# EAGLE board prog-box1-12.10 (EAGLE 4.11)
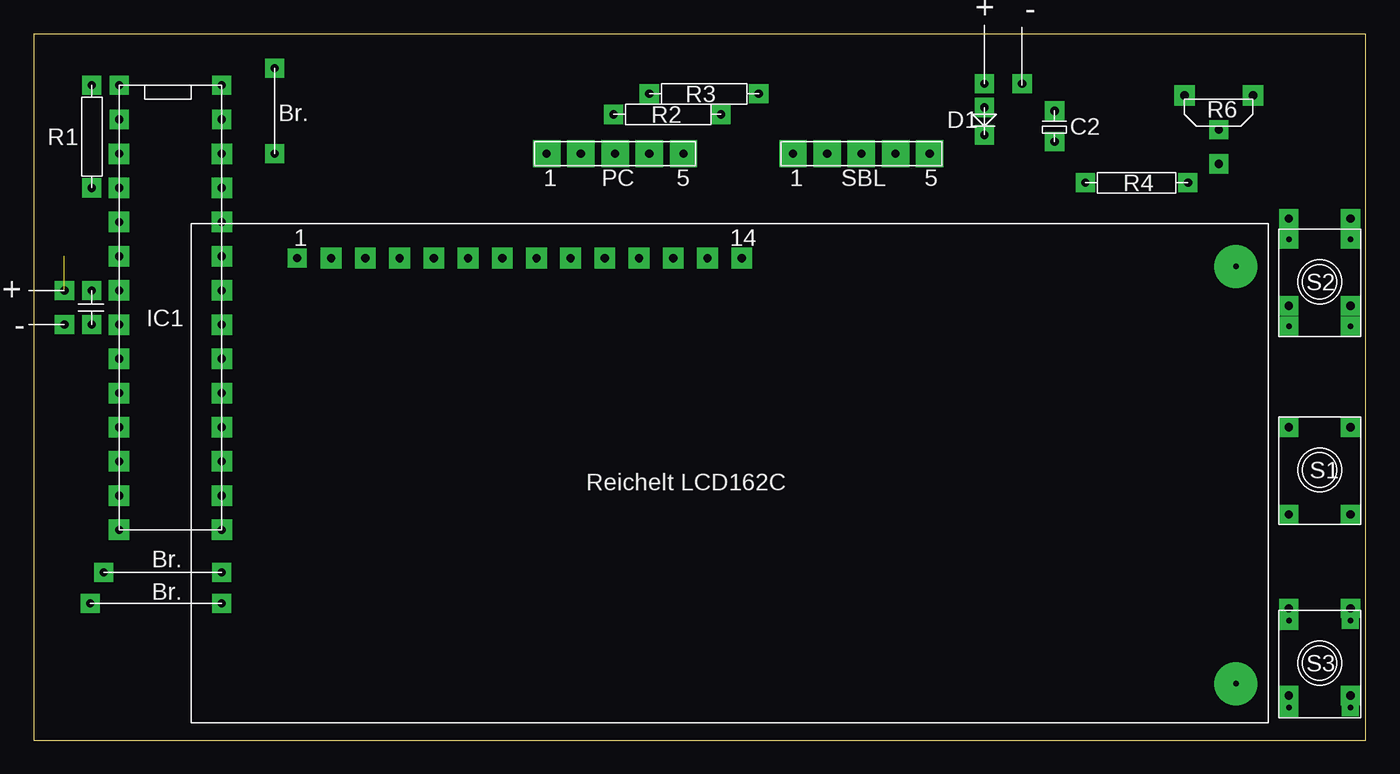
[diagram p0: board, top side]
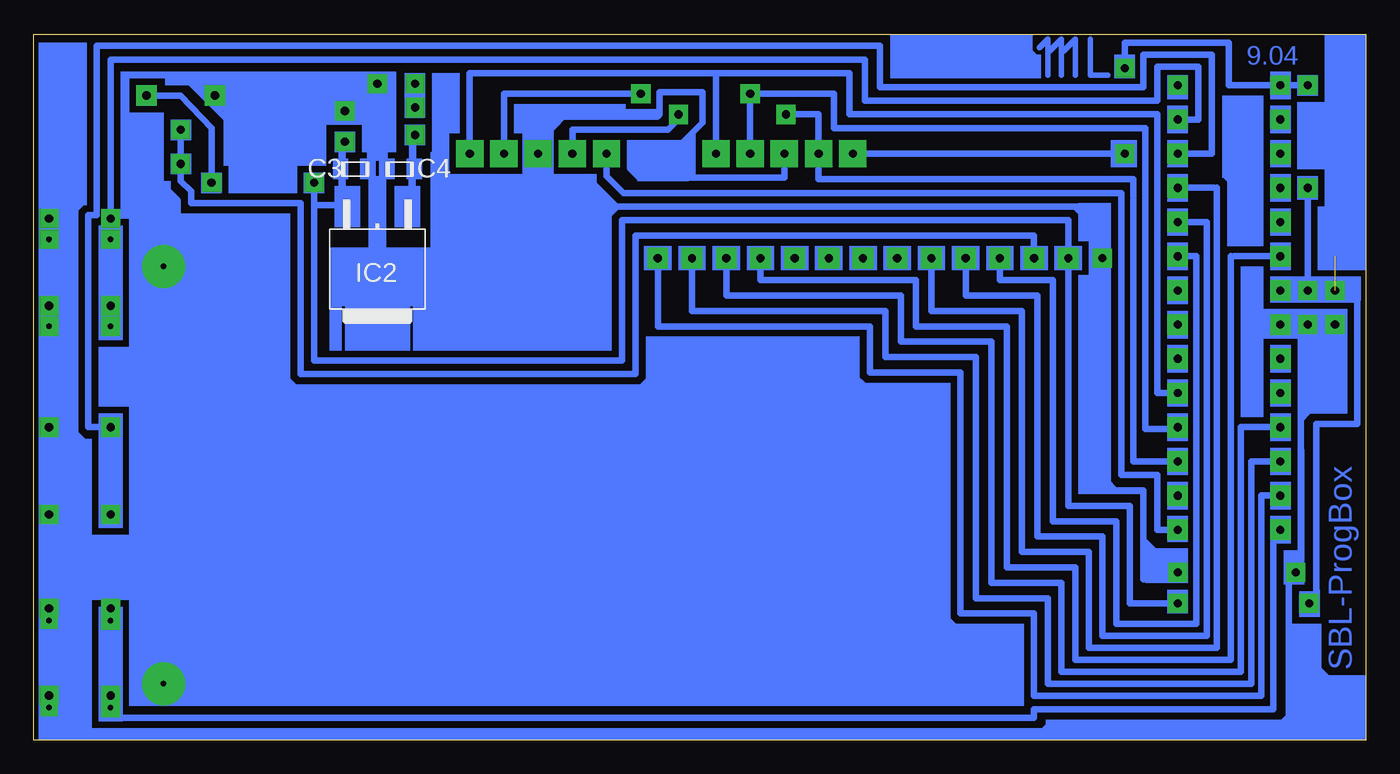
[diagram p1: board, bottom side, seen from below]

Size 98.93 x 52.45 mm. Coordinates in mm from the lower left corner, seen from the top.
Outline: 0,0 98.93,0 98.93,52.45 0,52.45 0,0
Copper layers (1*16): Top 0.035mm / dielectric 1.5mm / Bottom 0.035mm
Design rules "default": minimum track width 10mil, minimum drill 24mil, track to track 8mil, track to pad 8mil, pad to pad 8mil, via to via 8mil, smd to smd 8mil, copper to edge 40mil, drill to drill 8mil, minimum pad ring 10mil, minimum via ring 8mil, stop-mask expansion 4mil, vias tented up to drill 0mil, thermal gap 10mil

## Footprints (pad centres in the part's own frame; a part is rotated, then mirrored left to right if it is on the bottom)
LÖTMF = drill 0.61 pad 1.524 square: P$1 0,0; P$2 2.54,0; P$3 -2.54,0
LÖTP3 = drill 0.61 pad 1.422 square: P$1 0,0
LÖTD = drill 0.61 pad 1.524 square: P$2 2.54,0; P$3 -2.54,0

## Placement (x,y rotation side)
E$1  [LÖTMF]  6.35,18.16 90 top
E$2  [LÖTMF]  6.35,25.78 90 top
E$3  [LÖTMF]  6.35,33.4 90 top
E$4  [LÖTMF]  6.35,41.02 90 top
E$5  [LÖTP3]  6.35,46.1 0 top
E$6  [LÖTP3]  6.35,48.64 0 top
E$7  [LÖTMF]  13.97,18.16 90 top
E$8  [LÖTMF]  13.97,25.78 90 top
E$9  [LÖTMF]  13.97,33.4 90 top
E$10  [LÖTMF]  13.97,41.02 90 top
E$11  [LÖTP3]  13.97,46.1 0 top
E$12  [LÖTP3]  13.97,48.64 0 top
E$13  [LÖTMF]  50.04,35.81 180 top
E$14  [LÖTMF]  42.42,35.81 180 top
E$15  [LÖTMF]  34.8,35.81 180 top
E$16  [LÖTMF]  27.18,35.81 180 top
E$17  [LÖTP3]  22.1,35.81 90 top
E$18  [LÖTP3]  19.56,35.81 90 top
E$19  [LÖTMF]  45.72,43.56 180 top
E$20  [LÖTP3]  40.64,43.56 90 top
E$21  [LÖTP3]  38.1,43.56 90 top
E$22  [LÖTP3]  2.29,30.86 90 top
E$23  [LÖTP3]  4.32,41.02 0 top
E$24  [LÖTMF]  50.04,35.81 180 top
E$25  [LÖTP3]  38.1,43.56 90 top
E$26  [LÖTP3]  4.32,30.86 90 top
E$27  [LÖTP3]  4.32,33.4 90 top
E$28  [LÖTP3]  13.97,12.45 90 top
E$29  [LÖTP3]  5.21,12.45 90 top
E$30  [LÖTP3]  13.97,10.16 90 top
E$31  [LÖTP3]  4.19,10.16 90 top
E$32  [LÖTP3]  93.22,38.73 180 top
E$33  [LÖTP3]  93.22,32.26 180 top
E$34  [LÖTP3]  78.11,41.4 270 top
E$35  [LÖTP3]  85.72,41.4 270 top
E$36  [LÖTD]  88.01,47.88 180 top
E$37  [LÖTP3]  88.01,45.34 0 top
E$38  [SDIODE]  73.41,35.56 180 top
E$39  [LÖTMF]  58.93,43.56 0 top
E$40  [LÖTP3]  64.01,43.56 270 top
E$41  [LÖTP3]  66.55,43.56 270 top
E$42  [LÖTP3]  43.05,46.48 0 top
E$43  [LÖTP3]  51.05,46.48 0 top
E$44  [LÖTP3]  45.72,48.01 0 top
E$45  [LÖTP3]  53.85,48.01 0 top
E$46  [LÖTP3]  88.01,42.8 0 top
E$47  [LÖTP3]  70.61,46.99 90 top
E$48  [LÖTP3]  4.32,48.64 0 top
E$49  [LÖTP3]  17.91,43.56 90 top
E$50  [LÖTMF]  6.35,18.16 90 top
E$51  [LÖTMF]  13.97,18.16 90 top
E$52  [LÖTP3]  17.91,49.91 90 top
E$53  [0805]  71.75,42.42 0 bottom
E$54  [0805]  75.06,42.42 0 bottom
E$55  [LÖTP3]  75.82,44.45 90 top
E$56  [LÖTP3]  75.82,46.74 90 top
E$58  [LÖTP3]  73.41,48.77 90 top
E$59  [LÖTP3]  70.61,48.77 90 top
E$60  [LÖTP3]  70.61,44.96 90 top
E$62  [LÖTP3]  2.29,33.4 90 top
E$72  [LÖTP3]  97.79,38.73 180 top
E$73  [LÖTP3]  97.79,32.26 180 top
E$74  [LÖTP3]  93.22,38.73 180 top
E$75  [LÖTP3]  93.22,32.26 180 top
E$76  [LÖTP3]  97.79,38.73 180 top
E$77  [LÖTP3]  97.79,32.26 180 top
E$78  [LÖTP3]  93.22,23.24 180 top
E$79  [LÖTP3]  93.22,16.76 180 top
E$80  [LÖTP3]  97.79,23.24 180 top
E$81  [LÖTP3]  97.79,16.76 180 top
E$82  [LÖTP3]  93.22,23.24 180 top
E$83  [LÖTP3]  93.22,16.76 180 top
E$84  [LÖTP3]  97.79,23.24 180 top
E$85  [LÖTP3]  97.79,16.76 180 top
E$86  [LÖTP3]  93.22,9.78 180 top
E$87  [LÖTP3]  93.22,3.3 180 top
E$88  [LÖTP3]  97.79,9.78 180 top
E$89  [LÖTP3]  97.79,3.3 180 top
E$90  [LÖTP3]  93.22,9.78 180 top
E$91  [LÖTP3]  93.22,3.3 180 top
E$92  [LÖTP3]  97.79,9.78 180 top
E$93  [LÖTP3]  97.79,3.3 180 top

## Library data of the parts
E$1-E$37 E$39-E$52 E$55 E$56 E$58-E$60 E$62 E$72-E$93 = lötp
E$38 E$53 E$54 = SMD-MYneu

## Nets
S$7: E$50.P$1

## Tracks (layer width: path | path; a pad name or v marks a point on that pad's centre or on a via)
S$1
  Bottom 0.406: 5.71,48.64 5.71,48.51
  Bottom 0.5: 4.83,48.64 5.71,48.64
S$2
  Bottom 0.406: 6.86,48.64 6.86,48.51
  Bottom 0.5: 6.86,48.64 10.16,48.64 10.16,51.82 17.91,51.82 17.91,50.42
S$3
  Bottom 0.5: 38.35,49.4 38.35,46.48 15.49,46.48 15.49,38.73
S$4
  Bottom 0.406: 70.74,40.39 70.87,40.89 70.74,40.77 70.74,42.04
  Bottom 0.5: 70.87,40.89 70.87,42.04
S$5
  Bottom 0.5: 89.92,47.88 88.01,47.88 85.72,45.47 85.72,42.04
S$6
  Bottom 0.406: 25.65,38.61 25.27,38.61
  Bottom 0.5: 78.11,40.89 78.11,28.19 55.24,28.19 55.24,38.61 25.65,38.61 22.1,38.61 22.1,36.32
S$8
  Bottom 0.406: 97.92,0.64 97.79,1.78
  Bottom 0.5: 5.71,0.64 97.92,0.64
S$9
  Bottom 0.406: 14.61,12.45 16.51,11.94 | 19.56,35.05 19.56,18.54 19.68,18.54 20.57,18.54
  Bottom 0.5: 19.68,18.54 16.51,18.54 16.51,11.94
S$10
  Bottom 0.406: 95.38,39.88 95.38,40.13 | 95.38,39.88 96.14,39.12 | 95.25,40.01 95.38,39.88
S$11
  Bottom 0.5: 4.32,34.16 4.32,40.51
S$12
  Bottom 0.406: 9.65,40.89 9.65,41.15 10.41,41.91
S$13
  Bottom 0.5: 4.95,33.4 5.71,33.4
S$14
  Bottom 0.5: 1.65,33.4 0.64,33.4
S$15
  Bottom 0.406: 12.57,17.4 12.57,17.02
  Bottom 0.5: 13.46,35.94 12.57,35.94 12.57,17.4 12.57,8.64
S$16
  Bottom 0.5: 13.34,43.56 11.43,43.56 11.43,50.93 16.51,50.93
S$17
  Bottom 0.406: 62.48,40.01 61.47,40.01 61.47,43.05
S$18
  Bottom 0.5: 27.18,34.16 27.18,35.18 | 27.18,34.16 23.24,34.16 23.24,16.26 18.54,16.26 18.54,8.64 12.57,8.64 | 27.18,34.16 27.18,35.18 | 27.18,34.16 27.18,35.18
S$19
  Bottom 0.5: 22.1,35.18 22.1,17.4 17.53,17.4 17.53,10.16 14.48,10.16
S$20
  Bottom 0.5: 3.68,10.67 3.68,23.5 0.64,23.5 0.64,33.27
S$21
  Bottom 0.5: 37.21,47.5 37.21,50.55
S$22
  Bottom 0.406: 76.07,41.53 76.07,42.16 | 76.07,40.64 75.95,40.64
  Bottom 0.5: 76.07,40.64 76.07,41.53 76.07,43.94
S$23
  Bottom 0.406: 14.22,50.04 14.1,50.04
  Bottom 0.5: 37.21,47.5 15.49,47.5 15.49,50.04 14.22,50.04 12.45,50.04 12.45,46.1 13.34,46.1
S$24
  Bottom 0.406: 75.95,41.02 75.95,43.94
S$25
  Bottom 0.406: 24.26,51.44 23.62,52.07 23.62,49.4
S$26
  Bottom 0.5: 4.83,12.83 4.83,30.1
S$27
  Bottom 0.406: 19.56,36.45 19.56,38.86
S$28
  Bottom 0.406: 18.16,39.75 18.16,40.01 | 18.16,38.1 18.16,38.61 | 18.16,36.7 18.16,36.96
  Bottom 0.5: 14.61,15.62 15.49,15.62 15.49,19.68 18.16,19.68 18.16,36.7 18.16,38.1 18.16,39.75 18.16,40.64 55.12,40.64 56.39,41.91 56.39,43.05
S$29
  Bottom 0.406: 32.26,35.18 32.26,34.92 32.26,32.51
  Bottom 0.5: 32.26,34.92 32.26,31.88 25.53,31.88 25.53,13.97 20.57,13.97 20.57,6.86 11.05,6.86 11.05,16.76
S$30
  Bottom 0.406: 11.81,17.91 11.81,17.14
  Bottom 0.5: 13.08,38.48 11.81,38.48 11.81,17.91 11.81,7.75 19.56,7.75 19.56,15.11 24.38,15.11 24.38,33.02 29.72,33.02 29.72,35.18
S$31
  Bottom 0.5: 11.3,41.02 13.34,41.02
S$32
  Bottom 0.5: 11.05,16.38 11.05,41.02
S$33
  Bottom 0.5: 44.96,35.05 44.96,34.16 33.4,34.16 33.4,30.73 26.67,30.73 26.67,12.83 21.59,12.83 21.59,5.97 10.03,5.97
S$34
  Bottom 0.5: 36.07,48.51 16.51,48.51 16.51,50.93
S$35
  Bottom 0.406: 85.47,49.28 85.47,49.4 91.19,49.4 | 85.47,49.28 85.47,48.51 | 91.19,49.4 91.31,49.4 | 91.19,49.4 92.2,49.4 92.2,46.35 91.57,46.35 91.57,13.46 97.79,13.46 97.79,16.13 | 85.47,49.28 73.41,49.28
S$36
  Bottom 0.406: 17.27,40.26 17.27,40.13 17.27,40.39 17.27,40.51
  Bottom 0.5: 40.64,42.93 40.64,41.66 17.27,41.66 17.27,40.39 | 17.27,40.13 17.27,20.7 14.61,20.7
S$37
  Bottom 0.5: 37.21,50.55 93.22,50.55 93.22,37.85
S$38
  Bottom 0.5: 36.07,48.51 36.07,51.56
S$39
  Bottom 0.5: 52.58,35.31 52.58,30.73 36.83,30.73 36.83,27.3 30.1,27.3 30.1,9.4 24.64,9.4 24.64,3.3 7.87,3.3
S$40
  Bottom 0.5: 14.61,23.11 16.38,23.11 16.38,45.47 39.5,45.47 39.5,48.01 45.21,48.01
S$41
  Bottom 0.406: 23.5,51.18 22.61,52.07 22.61,49.4
S$42
  Bottom 0.5: 15.49,25.78 15.49,38.99
S$43
  Bottom 0.5: 14.61,25.78 15.37,25.78
S$44
  Bottom 0.5: 93.22,1.91 93.22,1.65 24.64,1.65 24.64,2.29 6.86,2.29 6.86,15.11
S$45
  Bottom 0.406: 22.48,51.18 21.59,52.07 21.59,49.4
S$46
  Bottom 0.406: 7.75,15.37 7.75,15.24
  Bottom 0.5: 6.86,18.16 7.75,18.16 7.75,15.37 7.75,3.3
S$47
  Bottom 0.5: 50.29,43.81 50.29,43.69 | 50.29,43.81 50.29,44.83 | 50.29,43.81 50.29,41.78 43.18,41.78 43.18,42.8
S$48
  Bottom 0.5: 93.22,31.37 93.22,36.58
S$49
  Bottom 0.406: 9.27,14.48 9.27,14.22
  Bottom 0.5: 6.99,23.24 9.27,23.24 9.27,14.48 9.27,5.08 22.61,5.08 22.61,11.68 27.81,11.68 27.81,29.59 34.54,29.59 34.54,33.02 47.5,33.02 47.5,35.18
S$50
  Bottom 0.5: 40.64,44.32 40.64,46.48 42.55,46.48
S$51
  Bottom 0.406: 38.61,31.88 38.48,31.88 | 8.51,14.99 8.51,14.48
  Bottom 0.5: 50.04,35.18 50.04,31.88 38.61,31.88 35.69,31.88 35.69,28.45 28.96,28.45 28.96,10.54 23.62,10.54 23.62,4.19 8.51,4.19 8.51,14.99 8.51,20.7 6.86,20.7
S$52
  Bottom 0.5: 66.55,44.32 66.55,49.53 48.26,49.53 | 38.35,49.53 48.26,49.53 | 48.26,49.53 48.26,44.2
S$53
  Bottom 0.5: 58.93,44.2 58.93,45.34 52.45,45.34
S$54
  Bottom 0.5: 54.61,48.01 64.01,48.01 64.01,44.2
S$55
  Bottom 0.406: 10.03,35.94 9.78,35.94 9.53,35.94
  Bottom 0.5: 10.03,16.38 10.03,35.94 | 9.78,35.94 6.86,35.94
S$56
  Bottom 0.406: 20.45,52.07 20.45,49.4 19.18,49.4
S$57
  Bottom 0.5: 10.03,5.97 10.03,16.51
S$58
  Bottom 0.5: 5.71,1.4 5.71,11.94
S$59
  Bottom 0.5: 18.41,43.56 37.47,43.56
S$60
  Bottom 0.5: 52.32,45.34 51.82,45.34 51.18,45.97
S$61
  Bottom 0.406: 96.14,23.5 96.14,23.11 95.12,22.1
S$62
  Bottom 0.5: 53.59,46.48 55.75,46.48
S$63
  Bottom 0.5: 52.45,46.48 53.47,46.48 | 49.28,45.85 49.28,48.13 52.45,48.13 52.45,46.48 | 49.28,45.85 50.29,44.83 50.29,44.7 50.93,44.07 | 52.45,46.48 52.58,46.35 | 49.28,45.85 50.93,44.2
S$64
  Bottom 0.5: 20.83,39.62 56.26,39.62 56.39,39.5
S$65
  Bottom 0.406: 97.79,31.37 97.79,36.7
S$66
  Bottom 0.406: 93.22,17.4 93.22,22.61
S$67
  Bottom 0.406: 89.66,37.97 89.66,38.23
S$68
  Bottom 0.406: 93.22,3.05 93.22,8.26
S$69
  Bottom 0.406: 97.79,3.05 97.79,8.38
S$70
  Bottom 0.5: 70.61,47.5 70.61,48.26
S$71
  Bottom 0.406: 97.79,23.75 97.79,29.97
S$72
  Bottom 0.406: 73.41,45.09 73.41,45.97
S$73
  Bottom 0.406: 75.31,46.74 73.41,46.74 73.41,46.86 75.18,46.86
S$74
  Bottom 0.5: 24.64,36.32 24.64,37.47 54.23,37.47 54.23,27.18 79.12,27.18 79.12,39.88 87.25,39.88 87.25,40.77 88.01,41.53 88.01,42.29
S$75
  Bottom 0.406: 70.74,38.99 70.74,43.05
  Bottom 0.5: 70.74,43.05 70.74,44.32
S$76
  Bottom 0.406: 73.28,48.01 73.28,44.96 73.15,44.96
S$77
  Bottom 0.406: 75.95,39.75 75.95,38.73
  Bottom 0.5: 75.95,39.75 78.11,39.75
S$78
  Bottom 0.406: 61.21,40.13 61.21,40.01 66.8,40.01 66.8,30.86
S$79
  Bottom 0.5: 88.01,43.31 88.01,44.83
S$80
  Bottom 0.406: 73.28,45.97 73.28,47.75
S$81
  Bottom 0.5: 85.98,47.5 85.98,47.37 | 85.98,47.5 87.5,49.02 87,49.02 86.11,48.13 | 83.44,44.96 85.98,47.5
S$82
  Bottom 0.5: 6.6,0.89 4.7,2.79 4.57,2.79 4.57,2.41 2.79,0.64
S$83
  Bottom 0.406: 80.64,27.43 80.64,27.3 79.38,26.04
S$84
  Bottom 0.406: 55.63,39.62 56.52,38.73
S$85
  Bottom 0.406: 55.75,39.75 57.78,41.78
S$86
  Bottom 0.406: 38.23,27.43 38.23,27.3 36.96,26.04
S$87
  Bottom 0.406: 52.83,27.43 52.83,27.18 53.85,26.16
S$88
  Bottom 0.406: 70.74,35.43 70.87,35.56
S$89
  Bottom 0.1: 3.68,25.27 3.94,24.77 4.95,23.75 4.7,23.75 4.19,24.26 4.32,24.38 4.57,24.13 4.57,24.26 4.45,24.38
S$90
  Bottom 0.5: 45.72,44.2 45.72,47.37
S$91
  Bottom 0.406: 33.4,10.54 32.64,10.54 29.84,7.75
S$92
  Bottom 0.406: 19.81,19.18 19.18,19.18 18.67,18.67
S$93
  Bottom 0.406: 16.38,14.73 15.62,13.97 16.13,13.97 16.38,14.22
S$94
  Bottom 0.406: 95,1.14 94.87,1.14 94.87,1.52
S$95
  Bottom 0.5: 89.41,41.15 89.28,41.15 88.27,40.13
S$96
  Bottom 0.5: 88.77,40.26 88.65,40.39
S$97
  Bottom 0.5: 80.9,44.7 81.28,44.7
S$98
  Bottom 0.5: 2.92,33.4 3.81,33.4
S$99
  Bottom 0.5: 20.19,38.73 20.7,38.73 21.46,39.5
S$100
  Bottom 0.1: 3.94,24.64 4.7,23.88
S$101  (via drill 0.41 pad 3.2)
  other vias: 89.28,4.19
S$102  (via drill 0.41 pad 3.2)
  other vias: 89.28,35.18
S$103
  Bottom 0.5: 95.38,1.14 95.38,1.27
S$104
  Bottom 0.5: 23.5,1.14 24.13,0.51
S$105  (via drill 0.41 pad 1.27, 0.41 pad 1.42)
  other vias: 4.32,48.64 4.32,48.64
S$106  (via drill 0.41 pad 1.27, 0.41 pad 1.42)
  other vias: 4.32,41.02 4.32,41.02
S$107  (via drill 0.41 pad 1.27, 0.41 pad 1.42)
  other vias: 6.35,41.02 6.35,41.02
S$108  (via drill 0.41 pad 1.27, 0.41 pad 1.42)
  other vias: 6.35,43.56 6.35,43.56
S$109  (via drill 0.41 pad 1.27, 0.41 pad 1.42)
  other vias: 6.35,46.1 6.35,46.1
S$110  (via drill 0.41 pad 1.27, 0.41 pad 1.42)
  other vias: 6.35,48.64 6.35,48.64
S$111  (via drill 0.41 pad 1.27, 0.41 pad 1.42)
  other vias: 13.97,48.64 13.97,48.64
S$112  (via drill 0.41 pad 1.27, 0.41 pad 1.42)
  other vias: 13.97,46.1 13.97,46.1
S$113  (via drill 0.41 pad 1.27, 0.41 pad 1.42)
  other vias: 13.97,43.56 13.97,43.56
S$114  (via drill 0.41 pad 1.27, 0.41 pad 1.42)
  other vias: 13.97,41.02 13.97,41.02
S$115  (via drill 0.41 pad 1.27, 0.41 pad 1.42)
  other vias: 13.97,38.48 13.97,38.48
S$116  (via drill 0.41 pad 1.27, 0.41 pad 1.42)
  other vias: 6.35,38.48 6.35,38.48
S$117  (via drill 0.41 pad 1.27, 0.41 pad 1.42)
  other vias: 6.35,35.94 6.35,35.94
S$118  (via drill 0.41 pad 1.27, 0.41 pad 1.42)
  other vias: 13.97,35.94 13.97,35.94
S$119  (via drill 0.41 pad 1.27, 0.41 pad 1.42)
  other vias: 13.97,33.4 13.97,33.4
S$120  (via drill 0.41 pad 1.27, 0.41 pad 1.42)
  other vias: 13.97,30.86 13.97,30.86
S$121  (via drill 0.41 pad 1.27, 0.41 pad 1.42)
  other vias: 13.97,28.32 13.97,28.32
S$122  (via drill 0.41 pad 1.27, 0.41 pad 1.42)
  other vias: 13.97,25.78 13.97,25.78
S$123  (via drill 0.41 pad 1.27, 0.41 pad 1.42)
  other vias: 6.35,25.78 6.35,25.78
S$124  (via drill 0.41 pad 1.27, 0.41 pad 1.42)
  other vias: 6.35,28.32 6.35,28.32
S$125  (via drill 0.41 pad 1.27)
  other vias: 6.35,30.86
S$126  (via drill 0.41 pad 1.27, 0.41 pad 1.42)
  other vias: 6.35,33.4 6.35,33.4
S$127  (via drill 0.41 pad 1.27, 0.41 pad 1.42)
  other vias: 4.32,33.4 4.32,33.4
S$128  (via drill 0.41 pad 1.27, 0.41 pad 1.42)  (1 unrouted)
  other vias: 2.29,33.4 2.29,33.4
S$129  (via drill 0.41 pad 1.27)
  other vias: 2.29,30.86
S$130  (via drill 0.41 pad 1.27)
  other vias: 4.32,30.86
S$131  (via drill 0.41 pad 1.27, 0.41 pad 1.42)
  other vias: 6.35,23.24 6.35,23.24
S$132  (via drill 0.41 pad 1.27, 0.41 pad 1.42)
  other vias: 6.35,20.7 6.35,20.7
S$133  (via drill 0.41 pad 1.27, 0.41 pad 1.42)
  other vias: 6.35,18.16 6.35,18.16
S$134  (via drill 0.41 pad 1.27, 0.41 pad 1.42)
  other vias: 6.35,15.62 6.35,15.62
S$135  (via drill 0.41 pad 1.27, 0.41 pad 1.42)
  other vias: 13.97,15.62 13.97,15.62
S$136  (via drill 0.41 pad 1.27, 0.41 pad 1.42)
  other vias: 13.97,18.16 13.97,18.16
S$137  (via drill 0.41 pad 1.27, 0.41 pad 1.42)
  other vias: 13.97,20.7 13.97,20.7
S$138  (via drill 0.41 pad 1.27, 0.41 pad 1.42)
  other vias: 13.97,23.24 13.97,23.24
S$139  (via drill 0.41 pad 1.27, 0.41 pad 1.42)
  other vias: 13.97,12.45 13.97,12.45
S$140  (via drill 0.41 pad 1.27, 0.41 pad 1.42)
  other vias: 13.97,10.16 13.97,10.16
S$141  (via drill 0.41 pad 1.27, 0.41 pad 1.42)
  other vias: 4.19,10.16 4.19,10.16
S$142  (via drill 0.41 pad 1.27)
  other vias: 5.21,12.45
S$143  (via drill 0.41 pad 1.27, 0.41 pad 1.42)
  other vias: 17.91,49.91 17.91,49.91
S$144  (via drill 0.41 pad 1.27, 0.41 pad 1.42)
  other vias: 17.91,43.56 17.91,43.56
S$145  (via drill 0.41 pad 1.27)
  other vias: 19.56,35.81
S$146  (via drill 0.41 pad 1.27)
  other vias: 22.1,35.69
S$147  (via drill 0.41 pad 1.27)
  other vias: 24.64,35.69
S$148  (via drill 0.41 pad 1.27)
  other vias: 27.18,35.69 27.18,35.69 27.18,35.69
S$149  (via drill 0.41 pad 1.27)
  other vias: 29.72,35.69
S$150  (via drill 0.41 pad 1.27)
  other vias: 32.26,35.69
S$151  (via drill 0.41 pad 1.27)
  other vias: 34.8,35.69
S$152  (via drill 0.41 pad 1.27)
  other vias: 37.34,35.69
S$153  (via drill 0.41 pad 1.27)
  other vias: 39.88,35.69
S$154  (via drill 0.41 pad 1.27)
  other vias: 42.42,35.69
S$155  (via drill 0.41 pad 1.27)
  other vias: 44.96,35.69
S$156  (via drill 0.41 pad 1.27)
  other vias: 47.5,35.69
S$157  (via drill 0.41 pad 1.27)
  other vias: 50.04,35.69
S$158  (via drill 0.41 pad 1.27)
  other vias: 52.58,35.69
S$159  (via drill 0.41 pad 1.54)
  other vias: 38.1,43.56
S$160  (via drill 0.41 pad 1.54)
  other vias: 40.64,43.56
S$161  (via drill 0.41 pad 1.54)
  other vias: 43.18,43.56
S$162  (via drill 0.41 pad 1.54)
  other vias: 45.72,43.56
S$163  (via drill 0.41 pad 1.54)
  other vias: 48.26,43.56
S$164  (via drill 0.41 pad 2.03)
  other vias: 40.64,43.56
S$165  (via drill 0.41 pad 2.03)
  other vias: 58.93,43.56
S$166  (via drill 0.41 pad 1.27, 0.41 pad 1.42)
  other vias: 53.85,48.01 53.85,48.01
S$167  (via drill 0.41 pad 1.27, 0.41 pad 1.42)
  other vias: 45.72,48.01 45.72,48.01
S$168  (via drill 0.41 pad 1.27, 0.41 pad 1.42)
  other vias: 43.05,46.48 43.05,46.48
S$169  (via drill 0.41 pad 1.27, 0.41 pad 1.42)
  other vias: 51.05,46.48 51.05,46.48
S$170  (via drill 0.41 pad 2.03)
  other vias: 61.47,43.56
S$171  (via drill 0.41 pad 2.03)
  other vias: 64.01,43.56
S$172  (via drill 0.41 pad 2.03)
  other vias: 66.55,43.56
S$173  (via drill 0.41 pad 1.27, 0.41 pad 1.42)
  other vias: 70.61,48.77 70.61,48.77
S$174  (via drill 0.41 pad 1.27)
  other vias: 73.41,48.77
S$175  (via drill 0.41 pad 1.27, 0.41 pad 1.42)
  other vias: 70.61,46.99 70.61,46.99
S$176  (via drill 0.41 pad 1.27, 0.41 pad 1.42)
  other vias: 70.61,44.96 70.61,44.96
S$177  (via drill 0.41 pad 1.27)
  other vias: 75.82,46.74
S$178  (via drill 0.41 pad 1.27, 0.41 pad 1.42)
  other vias: 75.82,44.45 75.82,44.45
S$179  (via drill 0.41 pad 1.27)
  other vias: 78.11,41.4
S$180  (via drill 0.41 pad 1.27, 0.41 pad 1.42)
  other vias: 85.72,41.4 85.72,41.4
S$181  (via drill 0.41 pad 1.27, 0.41 pad 1.42)
  other vias: 88.01,42.8 88.01,42.8
S$182  (via drill 0.41 pad 1.27, 0.41 pad 1.42)
  other vias: 88.01,45.34 88.01,45.34
S$183  (via drill 0.41 pad 1.27)
  other vias: 85.47,47.88
S$184  (via drill 0.41 pad 1.27, 0.41 pad 1.42)
  other vias: 90.55,47.88 90.55,47.88
S$185  (via drill 0.41 pad 1.27, 0.41 pad 1.42)
  other vias: 93.22,37.21 93.22,37.21
S$186  (via drill 0.41 pad 1.27, 0.41 pad 1.42)
  other vias: 97.79,37.21 97.79,37.21
S$187  (via drill 0.41 pad 1.27, 0.41 pad 1.42)
  other vias: 93.22,30.73 93.22,30.73
S$188  (via drill 0.41 pad 1.27, 0.41 pad 1.42)
  other vias: 97.79,30.73 97.79,30.73
S$189  (via drill 0.41 pad 1.27, 0.41 pad 1.42)
  other vias: 93.22,23.24 93.22,23.24
S$190  (via drill 0.41 pad 1.27, 0.41 pad 1.42)
  other vias: 97.79,23.24 97.79,23.24
S$191  (via drill 0.41 pad 1.27, 0.41 pad 1.42)
  other vias: 93.22,16.76 93.22,16.76
S$192  (via drill 0.41 pad 1.27, 0.41 pad 1.42)
  other vias: 97.79,16.76 97.79,16.76
S$193  (via drill 0.41 pad 1.27, 0.41 pad 1.42)
  other vias: 93.22,8.89 93.22,8.89
S$194  (via drill 0.41 pad 1.27)
  other vias: 97.79,8.89
S$195  (via drill 0.41 pad 1.27, 0.41 pad 1.42)
  other vias: 93.22,2.41 93.22,2.41
S$196  (via drill 0.41 pad 1.27)
  other vias: 97.79,2.41
S$197
  Bottom 0.5: 59.94,46.48 59.94,46.35 60.58,45.72
S$198
  Bottom 0.5: 59.18,46.86 59.18,46.74 60.71,45.21 60.71,45.47 60.58,45.59
S$199
  Bottom 0.5: 53.85,41.78 53.98,41.78 54.61,42.42
S$200  (via drill 0.41 pad 2.03)
  other vias: 56.39,43.56
S$201  (via drill 0.41 pad 2.03)
  other vias: 48.26,43.56
S$202  (via drill 0.41 pad 2.03)
  other vias: 45.72,43.56
S$203  (via drill 0.41 pad 2.03)
  other vias: 43.18,43.56
S$204  (via drill 0.41 pad 2.03)
  other vias: 38.1,43.56
S$205
  Bottom 0.406: 70.87,43.05 70.87,44.32
S$206  (via drill 0.41 pad 1.54)
  other vias: 22.1,35.81
S$207  (via drill 0.41 pad 1.54)
  other vias: 24.64,35.81
S$208  (via drill 0.41 pad 1.54)
  other vias: 27.18,35.81
S$209  (via drill 0.41 pad 1.54)
  other vias: 29.72,35.81
S$210  (via drill 0.41 pad 1.54)
  other vias: 32.26,35.81
S$211  (via drill 0.41 pad 1.54)
  other vias: 34.8,35.81
S$212  (via drill 0.41 pad 1.54)
  other vias: 37.34,35.81
S$213  (via drill 0.41 pad 1.54)
  other vias: 39.88,35.81
S$214  (via drill 0.41 pad 1.54)
  other vias: 42.42,35.81
S$215  (via drill 0.41 pad 1.54)
  other vias: 44.96,35.81
S$216  (via drill 0.41 pad 1.54)
  other vias: 47.5,35.81
S$217  (via drill 0.41 pad 1.54)
  other vias: 50.04,35.81
S$218  (via drill 0.41 pad 1.54)
  other vias: 52.58,35.81
S$219
  Bottom 0.406: 25.4,51.56 25.4,51.44 24.64,50.67 | 25.4,51.56 25.4,51.82 | 24.51,50.67 25.4,51.56
S$220
  Bottom 0.406: 4.19,6.35 4.19,5.97 2.67,4.45 2.92,4.45 3.56,5.08
S$221
  Bottom 0.5: 93.73,23.24 94.87,23.24 94.87,38.99 94.23,38.99 94.23,51.56 36.07,51.56
(copper drawn outside any net)
  shapes: Bottom area x665

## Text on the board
Bottom: 9.04 | SBL-ProgBox
tNames: 9V | - | + | R3 | Br. | R2 | R6 | D1 | C2 | R1 | 1 | PC | 5 | 1 | SBL | 5 | R4 | 1 | 14 | + | S2 | - | BEC | IC1 | Reichelt LCD162C | S1 | Br. | Br. | S3
bNames: C4 | C3 | IC2
tValues: 5k | 1k | 47µ | 1k | 10k | 15k
bValues: 100n | 100n | L4941B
